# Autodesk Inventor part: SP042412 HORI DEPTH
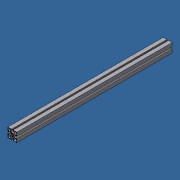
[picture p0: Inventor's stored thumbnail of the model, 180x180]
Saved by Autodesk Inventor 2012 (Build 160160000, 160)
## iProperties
Created: 2013-04
Part Number: SP042412 HORI DEPTH
Material: Aluminum-6061
Description: PROFILE 45X45 UL
Document SubType Name: Modeling
Designer: Admin
Stock Number: 20.1063 PROFILE 45X45 UL
Density: 2.71 g/cm^3
FINISH: CLEAR ANODIZED
Author: Admin
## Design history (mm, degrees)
sketch "Sketch1"
  geometry: L1 (-4.1, -22.5)-(-4.1, -18) reference; L2 (-4.6, -18)-(-6.8, -18) reference; L3 (-6.8, -18)-(-6.8, -9.5) reference; L4 (-6.8, -9.5)-(-4.5, -7.2) reference; L5 (-4.5, -7.2)-(4.5, -7.2) reference; L6 (4.5, -7.2)-(6.8, -9.5) reference; L7 (6.8, -9.5)-(6.8, -18) reference; L8 (4.1, -18)-(4.1, -22.5) reference; L9 (22.5, -22.5)-(4.4, -22.5) reference; L10 (22.5, -4.4)-(22.5, -22.5) reference; L11 (22.5, -4.1)-(18, -4.1) reference; L12 (18, -4.6)-(18, -6.8) reference; L13 (18, -6.8)-(9.5, -6.8) reference; L14 (9.5, -6.8)-(7.2, -4.5) reference; L15 (7.2, -4.5)-(7.2, 4.5) reference; L16 (7.2, 4.5)-(9.5, 6.8) reference; L17 (9.5, 6.8)-(18, 6.8) reference; L18 (18, 4.1)-(22.5, 4.1) reference; L19 (4.4, 22.5)-(22.5, 22.5) reference; L20 (4.1, 22.5)-(4.1, 18) reference; L21 (4.6, 18)-(6.8, 18) reference; L22 (6.8, 18)-(6.8, 9.5) reference; L23 (6.8, 9.5)-(4.5, 7.2) reference; L24 (4.5, 7.2)-(-4.5, 7.2) reference; L25 (-4.5, 7.2)-(-6.8, 9.5) reference; L26 (-6.8, 9.5)-(-6.8, 18) reference; L27 (-4.1, 18)-(-4.1, 22.5) reference; L28 (-22.5, 4.1)-(-18, 4.1) reference; L29 (-18, 4.6)-(-18, 6.8) reference; L30 (-18, 6.8)-(-9.5, 6.8) reference; L31 (-9.5, 6.8)-(-7.2, 4.5) reference; L32 (-7.2, 4.5)-(-7.2, -4.5) reference; L33 (-7.2, -4.5)-(-9.5, -6.8) reference; L34 (-9.5, -6.8)-(-18, -6.8) reference; L35 (-18, -4.1)-(-22.5, -4.1) reference; L36 (-22.5, -22.5)-(-22.5, -4.4) reference; L37 (-21.1, -6.5)-(-19.4, -6.5) reference; L38 (-19.4, -6.5)-(-19.4, -8.2) reference; L39 (-8.2, -19.4)-(-6.5, -19.4) reference; L40 (-6.5, -19.4)-(-6.5, -21.1) reference; L41 (6.5, -21.1)-(6.5, -19.4) reference; L42 (6.5, -19.4)-(8.2, -19.4) reference; L43 (19.4, -8.2)-(19.4, -6.5) reference; L44 (19.4, -6.5)-(21.1, -6.5) reference; L45 (21.1, 6.5)-(19.4, 6.5) reference; L46 (19.4, 6.5)-(19.4, 8.2) reference; L47 (8.2, 19.4)-(6.5, 19.4) reference; L48 (6.5, 19.4)-(6.5, 21.1) reference; L49 (-6.5, 21.1)-(-6.5, 19.4) reference; L50 (-6.5, 19.4)-(-8.2, 19.4) reference; L51 (-19.4, 8.2)-(-19.4, 6.5) reference; L52 (-19.4, 6.5)-(-21.1, 6.5) reference; L53 (-3.537, -5.8)-(-1.188, -3.451) reference; L54 (-3.451, -1.188)-(-5.8, -3.537) reference; L55 (-5.8, -3.537)-(-5.8, 3.537) reference; L56 (-5.8, 3.537)-(-3.451, 1.188) reference; L57 (-1.188, 3.451)-(-3.537, 5.8) reference; L58 (-3.537, 5.8)-(3.537, 5.8) reference; L59 (3.537, 5.8)-(1.188, 3.451) reference; L60 (3.451, 1.188)-(5.8, 3.537) reference; L61 (5.8, 3.537)-(5.8, -3.537) reference; L62 (5.8, -3.537)-(3.451, -1.188) reference; L63 (1.188, -3.451)-(3.537, -5.8) reference; L64 (3.537, -5.8)-(-3.537, -5.8) reference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; A1 r 3.65 centre (0, 0) between (3.287, 1.588) and (1.588, 3.287) reference; A2 r 3.65 centre (0, 0) between (1.588, 3.287) and (1.188, 3.451) reference; A3 r 3.65 centre (0, 0) between (-1.188, 3.451) and (-3.451, 1.188) reference; A4 r 3.65 centre (0, 0) between (-3.451, -1.188) and (-3.287, -1.588) reference; A5 r 3.65 centre (0, 0) between (-3.287, -1.588) and (-1.188, -3.451) reference; A6 r 3.65 centre (0, 0) between (1.188, -3.451) and (1.588, -3.287) reference; A7 r 3.65 centre (0, 0) between (1.588, -3.287) and (3.451, -1.188) reference; A8 r 3.65 centre (0, 0) between (3.451, 1.188) and (3.287, 1.588) reference
  constraints: 192 end point, 32 horizontal, 30 vertical, 16 point on circle, 8 centre point, 8 parallel, 5 perpendicular, 134 other
extrude "Extrusion1" new body sketch "Sketch1" stored distance "d0" = 773.6 (computed from DEPTH, TOP_OVERHANG); taper "d1" = 0 deg
body "Solid1"
other parameters: "Height" = 1066.8 [user parameter], "Width" = 1828.8 [user parameter], "DEPTH" = 914.4 [user parameter; used in 1 equation term], "LOWER_INSET" = 203.2 [user parameter], "TABLE_TOP_THICKNESS" = 12.7 [user parameter], "LEVELER_HEIGHT" = 115.824 [user parameter], "TOP_OVERHANG" = 25.4 [user parameter; used in 1 equation term]
